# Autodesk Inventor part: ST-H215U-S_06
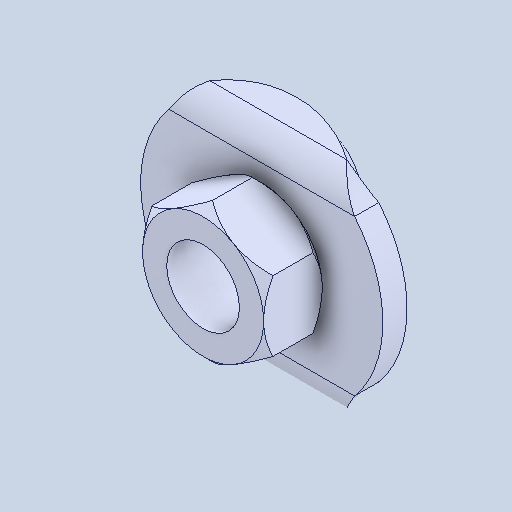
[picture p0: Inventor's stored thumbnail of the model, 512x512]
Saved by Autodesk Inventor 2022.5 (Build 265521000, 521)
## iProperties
Created: 2024-07
Part Number: ST-H215U-S_06
Material: 一般
Document SubType Name: Modeling
Designer: ImaoCorp
Density: 1 g/cm^3
Appearance: 既定
Author: ImaoCorp
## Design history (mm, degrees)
feature "ST-H215U-S_06"
node "ソリッド1"
